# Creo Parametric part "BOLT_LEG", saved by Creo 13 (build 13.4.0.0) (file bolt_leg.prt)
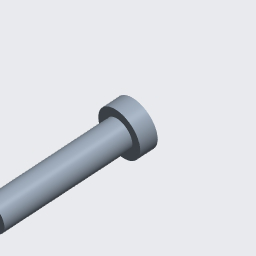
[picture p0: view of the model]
Units: millimeter Newton Second (mmNs); MM, TONNE, SECS

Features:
  1. datum plane "RIGHT"
  2. datum plane "TOP"
  3. datum plane "FRONT"
  4. coordinate system
  5. protrusion
  6. protrusion

Surfaces: 3 plane, 2 cylinder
